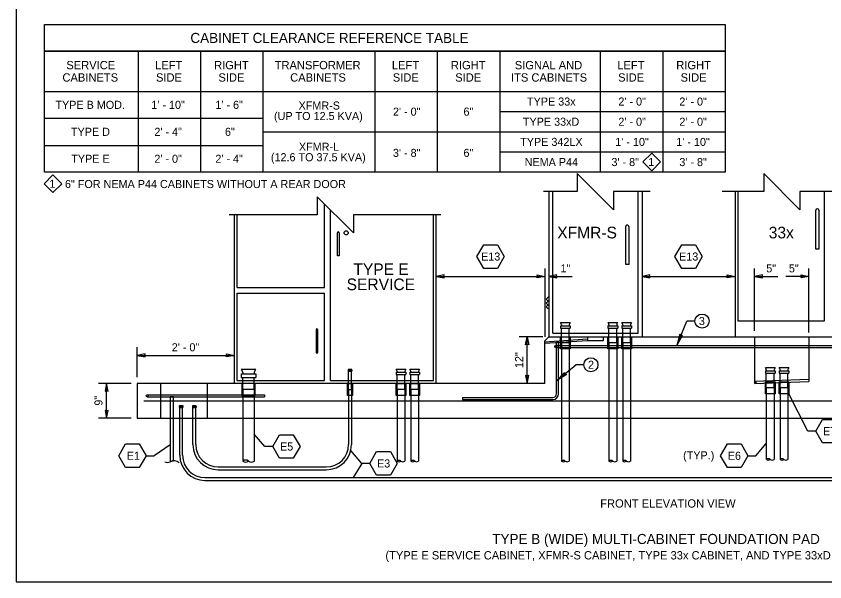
# Model space of a CAD drawing. Extents: x 99862 to 103151, y 100000 to 117076.
# Drawn here: x 99862 to 101465, y 115000 to 116121 of the extents above; entities that cross this region are included whole.
import ezdxf

# ---------------------------------------------------------------- set-up
doc = ezdxf.new("R2010")
doc.units = 0
for name, color, linetype in [('Default', 7, 'Continuous'), ('Level 1', 7, 'Continuous'), ('Level 11', 7, 'Continuous'), ('Level 15', 7, 'Continuous'), ('Level 20', 7, 'Continuous'), ('Level 3', 7, 'Continuous'), ('Level 40', 7, 'Continuous'), ('Level 6', 7, 'Continuous'), ('Level 60', 7, 'Continuous'), ('Level 8', 7, 'Continuous')]:
    doc.layers.add(name, color=color, linetype=linetype)

msp = doc.modelspace()

# ---------------------------------------------------------------- linework, layer by layer
at = {"layer": 'Default'}
for p, q in [((100994.7, 115480.7), (100910.1, 115475.1)), ((100994.7, 115477.8), (100910.1, 115472.2)), ((100931.3, 115468.2), (102016.3, 115468.2)), ((100933.2, 115372.6), (100933.2, 115473.9)), ((100937, 115473.9), (100933.2, 115473.9)), ((100937, 115372.6), (100937, 115473.9)), ((100931.3, 115464.3), (102016.3, 115464.3)), ((100121.9, 115370.1), (100354.5, 115370.1)), ((100354.5, 115370.1), (100354.5, 115366.3)), ((100121.9, 115366.3), (100354.5, 115366.3)), ((100746.6, 115364.9), (100925.5, 115364.9)), ((100746.6, 115364.9), (100746.6, 115361.1)), ((100746.6, 115361.1), (100925.5, 115361.1))]:
    msp.add_line(p, q, dxfattribs=at)
for centre, radius in [((100931.3, 115466.3), 1.92), ((101327.1, 115394.6), 1.44), ((100121.9, 115368.2), 1.92)]:
    msp.add_circle(centre, radius, dxfattribs=at)
for radius in [7.7, 11.5]:
    msp.add_arc((100925.5, 115372.6), radius, 270, 0, dxfattribs=at)
at = {"layer": 'Level 1'}
for p, q in [((100940.9, 115513.8), (100960.1, 115513.8)), ((101035, 115513.8), (101054.2, 115513.8)), ((101062.2, 115513.8), (101081.5, 115513.8)), ((100940.9, 115507.5), (100940.9, 115502.9)), ((100940.9, 115507.5), (100960.1, 115507.5)), ((100940.9, 115502.9), (100960.1, 115502.9)), ((100942.8, 115509.2), (100942.8, 115507.5)), ((100942.8, 115473.6), (100942.8, 115502.9)), ((100958.2, 115509.2), (100958.2, 115507.5)), ((100958.2, 115473.6), (100958.2, 115502.9)), ((100960.1, 115507.5), (100960.1, 115502.9)), ((101035, 115507.5), (101035, 115502.9)), ((101035, 115507.5), (101054.2, 115507.5)), ((101035, 115502.9), (101054.2, 115502.9)), ((101036.9, 115509.2), (101036.9, 115507.5)), ((101036.9, 115473.6), (101036.9, 115502.9)), ((101052.3, 115509.2), (101052.3, 115507.5)), ((101052.3, 115473.6), (101052.3, 115502.9)), ((101054.2, 115507.5), (101054.2, 115502.9)), ((101062.2, 115507.5), (101062.2, 115502.9)), ((101062.2, 115507.5), (101081.5, 115507.5)), ((101062.2, 115502.9), (101081.5, 115502.9)), ((101064.1, 115509.2), (101064.1, 115507.5)), ((101064.1, 115473.6), (101064.1, 115502.9)), ((101079.5, 115509.2), (101079.5, 115507.5)), ((101079.5, 115473.6), (101079.5, 115502.9)), ((101081.5, 115507.5), (101081.5, 115502.9)), ((100958.2, 115473.6), (100942.8, 115473.6)), ((100942.8, 115473.6), (100942.8, 115239.1)), ((100958.2, 115473.6), (100958.2, 115239.1)), ((101052.3, 115473.6), (101036.9, 115473.6)), ((101036.9, 115473.6), (101036.9, 115239.1)), ((101052.3, 115473.6), (101052.3, 115239.1)), ((101079.5, 115473.6), (101064.1, 115473.6)), ((101064.1, 115473.6), (101064.1, 115239.1)), ((101079.5, 115473.6), (101079.5, 115239.1)), ((100308.1, 115421.4), (100336.9, 115421.4)), ((100520, 115421.4), (100527.2, 115421.4)), ((100520, 115419.1), (100520, 115417.4)), ((100520, 115419.1), (100527.2, 115419.1)), ((100520, 115417.4), (100527.2, 115417.4)), ((100520.7, 115419.7), (100520.7, 115419.1)), ((100520.7, 115381.2), (100520.7, 115417.4)), ((100526.5, 115419.7), (100526.5, 115419.1)), ((100526.5, 115381.2), (100526.5, 115417.4)), ((100527.2, 115419.1), (100527.2, 115417.4)), ((100615, 115421.4), (100634.3, 115421.4)), ((100616.9, 115416.9), (100616.9, 115415.1)), ((100632.3, 115416.9), (100632.3, 115415.1)), ((100642.2, 115421.4), (100661.5, 115421.4)), ((100644.2, 115416.9), (100644.2, 115415.1)), ((100659.5, 115416.9), (100659.5, 115415.1)), ((101346.9, 115424.6), (101366.2, 115424.6)), ((101346.9, 115418.3), (101346.9, 115413.7)), ((101346.9, 115418.3), (101366.2, 115418.3)), ((101348.8, 115420.1), (101348.8, 115418.3)), ((101364.2, 115420.1), (101364.2, 115418.3)), ((101366.2, 115418.3), (101366.2, 115413.7)), ((101374.1, 115424.6), (101393.4, 115424.6)), ((101374.1, 115418.3), (101374.1, 115413.7)), ((101374.1, 115418.3), (101393.4, 115418.3)), ((101376.1, 115420.1), (101376.1, 115418.3)), ((101391.5, 115420.1), (101391.5, 115418.3)), ((101393.4, 115418.3), (101393.4, 115413.7)), ((100308.1, 115412), (100308.1, 115405.1)), ((100308.1, 115412), (100336.9, 115412)), ((100308.1, 115405.1), (100336.9, 115405.1)), ((100311, 115414.6), (100311, 115412)), ((100311, 115381.2), (100311, 115405.1)), ((100334, 115414.6), (100334, 115412)), ((100334, 115381.2), (100334, 115405.1)), ((100336.9, 115412), (100336.9, 115405.1)), ((100615, 115415.1), (100615, 115410.6)), ((100615, 115415.1), (100634.3, 115415.1)), ((100615, 115410.6), (100634.3, 115410.6)), ((100616.9, 115381.2), (100616.9, 115410.6)), ((100632.3, 115381.2), (100632.3, 115410.6)), ((100634.3, 115415.1), (100634.3, 115410.6)), ((100642.2, 115415.1), (100642.2, 115410.6)), ((100642.2, 115415.1), (100661.5, 115415.1)), ((100642.2, 115410.6), (100661.5, 115410.6)), ((100644.2, 115381.2), (100644.2, 115410.6)), ((100659.5, 115381.2), (100659.5, 115410.6)), ((100661.5, 115415.1), (100661.5, 115410.6)), ((101346.9, 115413.7), (101366.2, 115413.7)), ((101348.8, 115384.4), (101348.8, 115413.7)), ((101364.2, 115384.4), (101364.2, 115413.7)), ((101374.1, 115413.7), (101393.4, 115413.7)), ((101376.1, 115384.4), (101376.1, 115413.7)), ((101391.5, 115384.4), (101391.5, 115413.7)), ((101364.2, 115384.4), (101348.8, 115384.4)), ((101348.8, 115384.4), (101348.8, 115242.3)), ((101364.2, 115384.4), (101364.2, 115242.3)), ((101391.5, 115384.4), (101376.1, 115384.4)), ((101376.1, 115384.4), (101376.1, 115242.3)), ((101391.5, 115384.4), (101391.5, 115242.3)), ((100311, 115381.2), (100311, 115239.1)), ((100334, 115381.2), (100311, 115381.2)), ((100334, 115381.2), (100334, 115239.1)), ((100520.7, 115381.2), (100526.5, 115381.2)), ((100520.7, 115381.2), (100520.7, 115271.7)), ((100526.5, 115381.2), (100526.5, 115271.7)), ((100632.3, 115381.2), (100616.9, 115381.2)), ((100616.9, 115381.2), (100616.9, 115239.1)), ((100632.3, 115381.2), (100632.3, 115239.1)), ((100659.5, 115381.2), (100644.2, 115381.2)), ((100644.2, 115381.2), (100644.2, 115239.1)), ((100659.5, 115381.2), (100659.5, 115239.1)), ((100185.3, 115349.3), (100192.5, 115349.3)), ((100185.3, 115347), (100185.3, 115345.3)), ((100185.3, 115347), (100192.5, 115347)), ((100185.3, 115345.3), (100192.5, 115345.3)), ((100186.1, 115347.6), (100186.1, 115347)), ((100186.1, 115250.6), (100186.1, 115345.3)), ((100191.8, 115347.6), (100191.8, 115347)), ((100191.8, 115250.6), (100191.8, 115345.3)), ((100192.5, 115347), (100192.5, 115345.3)), ((100211.7, 115349.3), (100218.9, 115349.3)), ((100211.7, 115347), (100211.7, 115345.3)), ((100211.7, 115347), (100218.9, 115347)), ((100211.7, 115345.3), (100218.9, 115345.3)), ((100212.4, 115347.6), (100212.4, 115347)), ((100212.4, 115271.7), (100212.4, 115345.3)), ((100218.2, 115347.6), (100218.2, 115347)), ((100218.2, 115271.7), (100218.2, 115345.3)), ((100218.9, 115347), (100218.9, 115345.3)), ((100262.4, 115227.4), (100476.5, 115227.4)), ((100262.4, 115221.7), (100476.5, 115221.7)), ((100236.1, 115206.3), (102066.3, 115206.3)), ((100236.1, 115200.5), (102066.3, 115200.5))]:
    msp.add_line(p, q, dxfattribs=at)
for points in [[(99862, 114999.5), (103151, 114999.5), (103151, 117075.5), (99862, 117075.5)], [(100960.1, 115461.7), (100940.9, 115461.7), (100940.9, 115485.5), (100960.1, 115485.5)], [(101054.2, 115461.7), (101035, 115461.7), (101035, 115485.5), (101054.2, 115485.5)], [(101081.5, 115461.7), (101062.2, 115461.7), (101062.2, 115485.5), (101081.5, 115485.5)], [(100309, 115369.3), (100336, 115369.3), (100336, 115393.2), (100309, 115393.2)], [(100518.8, 115393.2), (100528.4, 115393.2), (100528.4, 115369.3), (100518.8, 115369.3)], [(100634.3, 115369.3), (100615, 115369.3), (100615, 115393.2), (100634.3, 115393.2)], [(100661.5, 115369.3), (100642.2, 115369.3), (100642.2, 115393.2), (100661.5, 115393.2)], [(101366.2, 115372.5), (101346.9, 115372.5), (101346.9, 115396.3), (101366.2, 115396.3)], [(101393.4, 115372.5), (101374.1, 115372.5), (101374.1, 115396.3), (101393.4, 115396.3)], [(100167.5, 115366.3), (100167.5, 115237.8), (100169.7, 115238.9), (100171.7, 115239.5), (100173.7, 115239.8), (100173.8, 115366.3)]]:
    msp.add_lwpolyline(points, close=True, dxfattribs=at)
for centre, radius, start, end in [((100936.5, 115509.2), 6.32, 0, 45.9402), ((100964.5, 115509.2), 6.32, 134.0598, 180), ((101030.6, 115509.2), 6.32, 0, 45.9402), ((101058.6, 115509.2), 6.32, 134.0598, 180), ((101057.8, 115509.2), 6.32, 0, 45.9402), ((101085.8, 115509.2), 6.32, 134.0598, 180), ((100301.5, 115414.6), 9.47, 0, 45.9402), ((100343.5, 115414.6), 9.47, 134.0598, 180), ((100518.4, 115419.7), 2.37, 0, 45.9402), ((100528.9, 115419.7), 2.37, 134.0598, 180), ((100610.6, 115416.9), 6.32, 0, 45.9402), ((100638.6, 115416.9), 6.32, 134.0598, 180), ((100637.8, 115416.9), 6.32, 0, 45.9402), ((100665.9, 115416.9), 6.32, 134.0598, 180), ((101342.5, 115420.1), 6.32, 0, 45.9402), ((101370.6, 115420.1), 6.32, 134.0598, 180), ((101369.7, 115420.1), 6.32, 0, 45.9402), ((101397.8, 115420.1), 6.32, 134.0598, 180), ((100183.7, 115347.6), 2.37, 0, 45.9402), ((100194.2, 115347.6), 2.37, 134.0598, 180), ((100210.1, 115347.6), 2.37, 0, 45.9402), ((100220.6, 115347.6), 2.37, 134.0598, 180), ((100262.4, 115271.7), 50, 180, 270), ((100262.4, 115271.7), 44.3, 180, 270), ((100476.5, 115271.7), 44.3, 270, 0), ((100476.5, 115271.7), 50, 270, 0), ((100236.1, 115250.6), 50, 180, 270), ((100236.1, 115250.6), 44.3, 180, 270), ((100316.7, 115232), 9.14, 50.8329, 129.1671), ((100620.8, 115234.4), 6.09, 50.8329, 129.1671), ((100648, 115234.4), 6.09, 50.8329, 129.1671), ((100946.6, 115234.4), 6.09, 50.8329, 129.1671), ((101040.8, 115234.4), 6.09, 50.8329, 129.1671), ((101068, 115234.4), 6.09, 50.8329, 129.1671), ((101352.7, 115237.6), 6.09, 50.8329, 129.1671), ((101352.7, 115247), 6.09, 230.8329, 309.1671), ((101360.4, 115247), 6.09, 230.8329, 309.1671), ((101379.9, 115237.6), 6.09, 50.8329, 129.1671), ((101379.9, 115247), 6.09, 230.8329, 309.1671), ((101387.6, 115247), 6.09, 230.8329, 309.1671), ((100161.2, 115251), 14.6, 250.7571, 295.3506), ((100174.7, 115225.7), 14.1, 42.3778, 121.1813), ((100316.7, 115246.2), 9.14, 230.8329, 309.1671), ((100328.3, 115246.2), 9.14, 230.8329, 309.1671), ((100620.8, 115243.8), 6.09, 230.8329, 309.1671), ((100628.5, 115243.8), 6.09, 230.8329, 309.1671), ((100648, 115243.8), 6.09, 230.8329, 309.1671), ((100655.7, 115243.8), 6.09, 230.8329, 309.1671), ((100946.6, 115243.8), 6.09, 230.8329, 309.1671), ((100954.3, 115243.8), 6.09, 230.8329, 309.1671), ((101040.8, 115243.8), 6.09, 230.8329, 309.1671), ((101048.5, 115243.8), 6.09, 230.8329, 309.1671), ((101068, 115243.8), 6.09, 230.8329, 309.1671), ((101075.7, 115243.8), 6.09, 230.8329, 309.1671)]:
    msp.add_arc(centre, radius, start, end, dxfattribs=at)
at = {"layer": 'Level 11'}
for p, q in [((100994.7, 115485.5), (100994.7, 115477.8)), ((101025.5, 115485.5), (101025.5, 115477.8)), ((101325.6, 115485.5), (101325.6, 115393.2)), ((101433.4, 115485.5), (101433.4, 115397)), ((101025.5, 115477.8), (100994.7, 115477.8)), ((101433.4, 115400.8), (101325.6, 115397)), ((100148.3, 115393.2), (100148.3, 115323.9)), ((100240.6, 115393.2), (100240.6, 115323.9)), ((101325.6, 115393.2), (101433.4, 115397))]:
    msp.add_line(p, q, dxfattribs=at)
for points in [[(100910.1, 115393.2), (100910.1, 115477.8), (100917.8, 115485.5)], [(100917.8, 115485.5), (102029.7, 115485.5)], [(100910.1, 115393.2), (100102.1, 115393.2)], [(100102.1, 115393.2), (100102.1, 115323.9)], [(100102.1, 115323.9), (102222.1, 115323.9)]]:
    msp.add_lwpolyline(points, dxfattribs=at)
at = {"layer": 'Level 15'}
for p, q in [((100910.1, 115621.3), (100910.1, 115485.5)), ((101325.6, 115497.5), (101325.6, 115621.3)), ((101433.3, 115493.9), (101433.3, 115621.3)), ((100694.6, 115605.3), (100910.1, 115605.3)), ((100917.8, 115605.3), (100964, 115605.3)), ((101102.5, 115605.3), (101287.2, 115605.3)), ((101325.6, 115605.3), (101371.8, 115605.3)), ((101433.3, 115605.3), (101387.2, 115605.3)), ((101171.2, 115468.2), (101191.4, 115516.7)), ((101207.4, 115516.7), (101191.4, 115516.7)), ((100905.8, 115485.5), (100858.9, 115485.5)), ((100874.9, 115393.2), (100874.9, 115485.5)), ((100102.1, 115405.2), (100102.1, 115464.7)), ((100102.1, 115448.7), (100294.5, 115448.7)), ((100933.2, 115398), (100971.1, 115430.1)), ((100987.1, 115430.1), (100971.1, 115430.1)), ((100090.1, 115393.2), (100025.2, 115393.2)), ((100041.2, 115323.9), (100041.2, 115393.2)), ((101430.9, 115298.3), (101393.4, 115372.5)), ((100090.1, 115323.9), (100025.2, 115323.9)), ((100354.7, 115267.9), (100334, 115292.4)), ((101446.9, 115298.3), (101430.9, 115298.3)), ((101328.2, 115249.5), (101348.8, 115274.1)), ((100167.5, 115271), (100135.5, 115249.5)), ((100370.7, 115267.9), (100354.7, 115267.9)), ((100547, 115234.3), (100525.1, 115259.7)), ((100119.5, 115249.5), (100135.5, 115249.5)), ((101312.2, 115249.5), (101328.2, 115249.5)), ((100547, 115234.3), (100530.1, 115206.3)), ((100563, 115234.3), (100547, 115234.3))]:
    msp.add_line(p, q, dxfattribs=at)
for points in [[(101118.6, 115773.5), (101046, 115773.5), (101046, 115737.6), (100974.2, 115809.4), (100974.2, 115773.5), (100907.2, 115773.5)], [(101488, 115773.5), (101415.4, 115773.5), (101415.4, 115737.6), (101343.6, 115809.4), (101343.6, 115773.5), (101261.1, 115773.5)], [(100703.6, 115727.3), (100530.5, 115727.3), (100530.5, 115691.4), (100458.7, 115763.2), (100458.7, 115727.3), (100284.4, 115727.3)]]:
    msp.add_lwpolyline(points, dxfattribs=at)
for points in [[(100694.6, 115605.3), (100710.4, 115602.2), (100709.6, 115605.3), (100710.4, 115608.3)], [(100910.1, 115605.3), (100894.4, 115602.2), (100895.1, 115605.3), (100894.4, 115608.3)], [(100917.8, 115605.3), (100933.5, 115602.2), (100932.8, 115605.3), (100933.5, 115608.3)], [(101102.5, 115605.3), (101118.2, 115602.2), (101117.5, 115605.3), (101118.2, 115608.3)], [(101287.2, 115605.3), (101271.4, 115602.2), (101272.2, 115605.3), (101271.4, 115608.3)], [(101325.6, 115605.3), (101341.4, 115602.2), (101340.6, 115605.3), (101341.4, 115608.3)], [(101433.3, 115605.3), (101417.6, 115602.2), (101418.3, 115605.3), (101417.6, 115608.3)], [(100874.9, 115485.5), (100878, 115469.8), (100874.9, 115470.5), (100871.8, 115469.8)], [(101171.2, 115468.2), (101182.7, 115488.1), (101179.5, 115488.3), (101177.2, 115490.4)], [(100102.1, 115448.7), (100117.9, 115445.7), (100117.1, 115448.7), (100117.9, 115451.8)], [(100294.5, 115448.7), (100278.8, 115445.7), (100279.5, 115448.7), (100278.8, 115451.8)], [(100874.9, 115393.2), (100878, 115408.9), (100874.9, 115408.1), (100871.8, 115408.9)], [(100933.2, 115398), (100948.7, 115415), (100949.8, 115412.1), (100952.5, 115410.5)], [(100041.2, 115393.2), (100038.1, 115377.4), (100041.2, 115378.2), (100044.2, 115377.4)], [(100041.2, 115323.9), (100044.2, 115339.6), (100041.2, 115338.9), (100038.1, 115339.6)]]:
    msp.add_lwpolyline(points, close=True, dxfattribs=at)
at = {"layer": 'Level 20'}
for points in [[(101121.7, 115849.8), (101139.3, 115832.3), (101121.7, 115814.7), (101104.2, 115832.3)], [(99934.8, 115806.8), (99952.4, 115789.2), (99934.8, 115771.7), (99917.3, 115789.2)]]:
    msp.add_lwpolyline(points, close=True, dxfattribs=at)
for points in [[(100775.3, 115644.7), (100788.8, 115668.1), (100815.9, 115668.1), (100829.4, 115644.7), (100815.9, 115621.3), (100788.8, 115621.3), (100775.3, 115644.7)], [(101167.8, 115644.7), (101181.3, 115668.1), (101208.4, 115668.1), (101221.9, 115644.7), (101208.4, 115621.3), (101181.3, 115621.3), (101167.8, 115644.7)], [(101446.9, 115298.3), (101460.4, 115321.8), (101487.4, 115321.8), (101501, 115298.3), (101487.4, 115274.9), (101460.4, 115274.9), (101446.9, 115298.3)], [(100370.7, 115267.9), (100384.2, 115291.3), (100411.3, 115291.3), (100424.8, 115267.9), (100411.3, 115244.5), (100384.2, 115244.5), (100370.7, 115267.9)], [(100065.4, 115249.5), (100078.9, 115272.9), (100106, 115272.9), (100119.5, 115249.5), (100106, 115226.1), (100078.9, 115226.1), (100065.4, 115249.5)], [(101258.1, 115249.5), (101271.7, 115273), (101298.7, 115273), (101312.2, 115249.5), (101298.7, 115226.1), (101271.7, 115226.1), (101258.1, 115249.5)], [(100563, 115234.3), (100576.5, 115257.7), (100603.6, 115257.7), (100617.1, 115234.3), (100603.6, 115210.8), (100576.5, 115210.8), (100563, 115234.3)]]:
    msp.add_lwpolyline(points, dxfattribs=at)
for centre in [(101221.4, 115516.7), (101001.1, 115430.1)]:
    msp.add_circle(centre, 14, dxfattribs=at)
at = {"layer": 'Level 3'}
for p, q in [((100473.4, 115583.6), (100473.4, 115748.5)), ((100485, 115398.9), (100485, 115736.9)), ((100294.5, 115393.2), (100294.5, 115727.3)), ((100300.3, 115583.6), (100300.3, 115727.3)), ((100688.9, 115398.9), (100688.9, 115727.3)), ((100694.6, 115393.2), (100694.6, 115727.3)), ((100498.6, 115689.4), (100498.6, 115691.7)), ((100498.6, 115646.3), (100498.6, 115689.4)), ((100502.1, 115691.7), (100502.1, 115689.4)), ((100502.1, 115689.4), (100502.1, 115646.3)), ((100502.1, 115646.3), (100498.6, 115646.3)), ((100300.3, 115583.6), (100473.4, 115583.6)), ((100300.3, 115398.9), (100300.3, 115572.1)), ((100300.3, 115572.1), (100473.4, 115572.1)), ((100473.4, 115398.9), (100473.4, 115572.1)), ((100456.3, 115499.3), (100456.3, 115497.1)), ((100456.3, 115497.1), (100456.3, 115453.9)), ((100459.7, 115497.1), (100459.7, 115499.3)), ((100459.7, 115453.9), (100459.7, 115497.1)), ((100456.3, 115453.9), (100459.7, 115453.9)), ((100300.3, 115398.9), (100473.4, 115398.9)), ((100485, 115398.9), (100688.9, 115398.9))]:
    msp.add_line(p, q, dxfattribs=at)
msp.add_circle((100516, 115691.7), 4.11, dxfattribs=at)
for centre in [(100500.3, 115691.7), (100458, 115499.3)]:
    msp.add_arc(centre, 1.71, 0, 180, dxfattribs=at)
at = {"layer": 'Level 40'}
for p, q in [((100103.6, 116052.1), (100103.6, 115812.1)), ((100227.4, 116052.1), (100227.4, 115812.1)), ((100351.2, 116052.1), (100351.2, 115812.1)), ((100572.9, 116052.1), (100572.9, 115812.1)), ((100696.7, 116052.1), (100696.7, 115812.1)), ((100820.5, 116052.1), (100820.5, 115812.1)), ((101019.6, 116052.1), (101019.6, 115812.1)), ((101143.4, 116052.1), (101143.4, 115812.1)), ((99918.1, 115972.1), (101267.2, 115972.1)), ((100820.5, 115932.1), (101267.2, 115932.1)), ((99918.1, 115919.1), (100351.2, 115919.1)), ((100351.2, 115892.1), (100820.5, 115892.1)), ((100809.5, 115892.1), (101267.2, 115892.1)), ((99918.1, 115865.1), (100351.2, 115865.1)), ((100820.5, 115852.1), (101267.2, 115852.1)), ((100115, 115358.5), (102209.3, 115358.5))]:
    msp.add_line(p, q, dxfattribs=at)
for points in [[(99918.1, 116104.8), (101267.2, 116104.8), (101267.2, 116052.1), (99918.1, 116052.1)], [(99918.1, 116052.1), (101267.2, 116052.1), (101267.2, 115812.1), (99918.1, 115812.1)]]:
    msp.add_lwpolyline(points, close=True, dxfattribs=at)
at = {"layer": 'Level 6'}
for p, q in [((101287.2, 115773.5), (101287.2, 115485.5)), ((101447, 115732.5), (101447, 115736.4)), ((101447, 115659.2), (101447, 115732.5)), ((101452.8, 115736.4), (101452.8, 115732.5)), ((101452.8, 115732.5), (101452.8, 115659.2)), ((101452.8, 115659.2), (101447, 115659.2))]:
    msp.add_line(p, q, dxfattribs=at)
msp.add_lwpolyline([(101463.2, 115773.5), (101463.2, 115516.4), (101293.3, 115516.4), (101293.3, 115773.5)], dxfattribs=at)
msp.add_arc((101449.9, 115736.4), 2.9, 0, 180, dxfattribs=at)
at = {"layer": 'Level 60'}
msp.add_line((99862, 114999.5), (99862, 114999.5), dxfattribs=at)
at = {"layer": 'Level 8'}
for p, q in [((100917.8, 115773.5), (100917.8, 115485.5)), ((100925.5, 115493), (100925.5, 115773.5)), ((101094.8, 115493), (101094.8, 115773.5)), ((101102.5, 115773.5), (101102.5, 115485.5)), ((101070.3, 115700.5), (101070.3, 115704.3)), ((101070.3, 115628.9), (101070.3, 115700.5)), ((101076.1, 115704.3), (101076.1, 115700.5)), ((101076.1, 115700.5), (101076.1, 115628.9)), ((101076.1, 115628.9), (101070.3, 115628.9)), ((100912.4, 115560), (100917.8, 115565.3)), ((100912.4, 115560), (100916.5, 115556)), ((100912.4, 115552.4), (100916.3, 115556.2)), ((100912.4, 115552.4), (100916.5, 115548.4)), ((100912.4, 115544.9), (100916.3, 115548.7)), ((100912.4, 115544.9), (100916.5, 115540.9)), ((100925.5, 115493), (101094.8, 115493))]:
    msp.add_line(p, q, dxfattribs=at)
msp.add_ellipse((101073.2, 115704.3), major_axis=(2.89, 0), ratio=0.979592, start_param=0, end_param=3.141593, dxfattribs=at)

# ---------------------------------------------------------------- texts
at = {"layer": 'Level 20'}
for s, height, p in [('CABINET CLEARANCE REFERENCE TABLE', 20, (100207.3, 116068.3)), ('SERVICE', 16.5, (99961.4, 116016.1)), ('LEFT', 16.5, (100137.4, 116016.1)), ('RIGHT', 16.5, (100254.3, 116016.1)), ('TRANSFORMER', 16.5, (100374.3, 116016.1)), ('LEFT', 16.5, (100606.7, 116016.1)), ('RIGHT', 16.5, (100723.6, 116016.1)), ('SIGNAL AND', 16.5, (100850.3, 116016.1)), ('LEFT', 16.5, (101053.4, 116016.1)), ('RIGHT', 16.5, (101170.3, 116016.1)), ('CABINETS', 16.5, (99953.7, 115991.6)), ('SIDE', 16.5, (100139.1, 115991.6)), ('SIDE', 16.5, (100262.9, 115991.6)), ('CABINETS', 16.5, (100405.1, 115991.6)), ('SIDE', 16.5, (100608.4, 115991.6)), ('SIDE', 16.5, (100732.2, 115991.6)), ('ITS CABINETS', 16.5, (100842.8, 115991.6)), ('SIDE', 16.5, (101055.1, 115991.6)), ('SIDE', 16.5, (101178.9, 115991.6)), ('TYPE B MOD.', 16, (99939.8, 115937.6)), ('1\' - 10"', 16, (100129.9, 115937.6)), ('1\' - 6"', 16, (100256.8, 115937.6)), ('XFMR-S', 16, (100421.7, 115936.2)), ('TYPE 33x', 16, (100874.5, 115944.1)), ('2\' - 0"', 16, (101055.6, 115944.1)), ('2\' - 0"', 16, (101176.4, 115944.1)), ('(UP TO 12.5 KVA)', 16, (100373, 115915.4)), ('2\' - 0"', 16, (100608.8, 115924.1)), ('6"', 16, (100748.6, 115924.1)), ('TYPE 33xD', 16, (100866.3, 115904.1)), ('2\' - 0"', 16, (101055.6, 115904.1)), ('2\' - 0"', 16, (101176.4, 115904.1)), ('TYPE D', 16, (99970.6, 115884.1)), ('2\' - 4"', 16, (100136, 115884.1)), ('6"', 16, (100275.8, 115884.1)), ('XFMR-L', 16, (100422.3, 115854.5)), ('TYPE 342LX', 16, (100861, 115864.1)), ('1\' - 10"', 16, (101049.5, 115864.1)), ('1\' - 10"', 16, (101170.4, 115864.1)), ('(12.6 TO 37.5 KVA)', 16, (100366.9, 115833.7)), ('3\' - 8"', 16, (100608.8, 115842.3)), ('6"', 16, (100748.6, 115842.3)), ('TYPE E', 16, (99971.2, 115830.6)), ('2\' - 0"', 16, (100135.9, 115830.6)), ('2\' - 4"', 16, (100256.8, 115830.6)), ('NEMA P44', 16, (100869.9, 115824.1)), ('3\' - 8"', 16, (101041.9, 115824.1)), ('1', 16, (101114.8, 115824.3)), ('3\' - 8"', 16, (101176.4, 115824.1)), ('1', 16, (99927.9, 115781.2)), ('6" FOR NEMA P44 CABINETS WITHOUT A REAR DOOR', 16, (99958.7, 115780.5)), ('E13', 16, (100783.5, 115636.7)), ('E13', 16, (101175.9, 115636.7)), ('1"', 16, (100940.8, 115613.3)), ('5"', 16, (101348.6, 115613.3)), ('5"', 16, (101393.5, 115613.3)), ('3', 16, (101215.2, 115508.8)), ('2\' - 0"', 16, (100170.4, 115456.7)), ('2', 16, (100995.3, 115422.1)), ('E7', 16, (101461.2, 115290.3)), ('E5', 16, (100384.9, 115259.9)), ('E1', 16, (100081.1, 115241.5)), ('(TYP.)', 16, (101183.9, 115242.4)), ('E6', 16, (101272.4, 115241.5)), ('E3', 16, (100577.2, 115226.3)), ('FRONT ELEVATION VIEW', 16.5, (101019.6, 115146.7)), ('TYPE B (WIDE) MULTI-CABINET FOUNDATION PAD', 20, (100805.6, 115074.5)), ('(TYPE E SERVICE CABINET, XFMR-S CABINET, TYPE 33x CABINET, AND TYPE 33xD CABINET SHOWN)', 16.5, (100593.8, 115043.9))]:
    msp.add_text(s, height=height, dxfattribs=at).set_placement(p)
for s, p in [('12"', (100866.9, 115423.5)), ('9"', (100033.2, 115348.9))]:
    msp.add_text(s, height=16, rotation=90, dxfattribs=at).set_placement(p)
at = {"layer": 'Level 6'}
for s, p in [('XFMR-S', (100934.4, 115680.7)), ('33x', (101353.6, 115680.7)), ('TYPE E', (100530.4, 115607.9)), ('SERVICE', (100517, 115578))]:
    msp.add_text(s, height=23.09, dxfattribs=at).set_placement(p)

doc.saveas('drawing.dxf')
